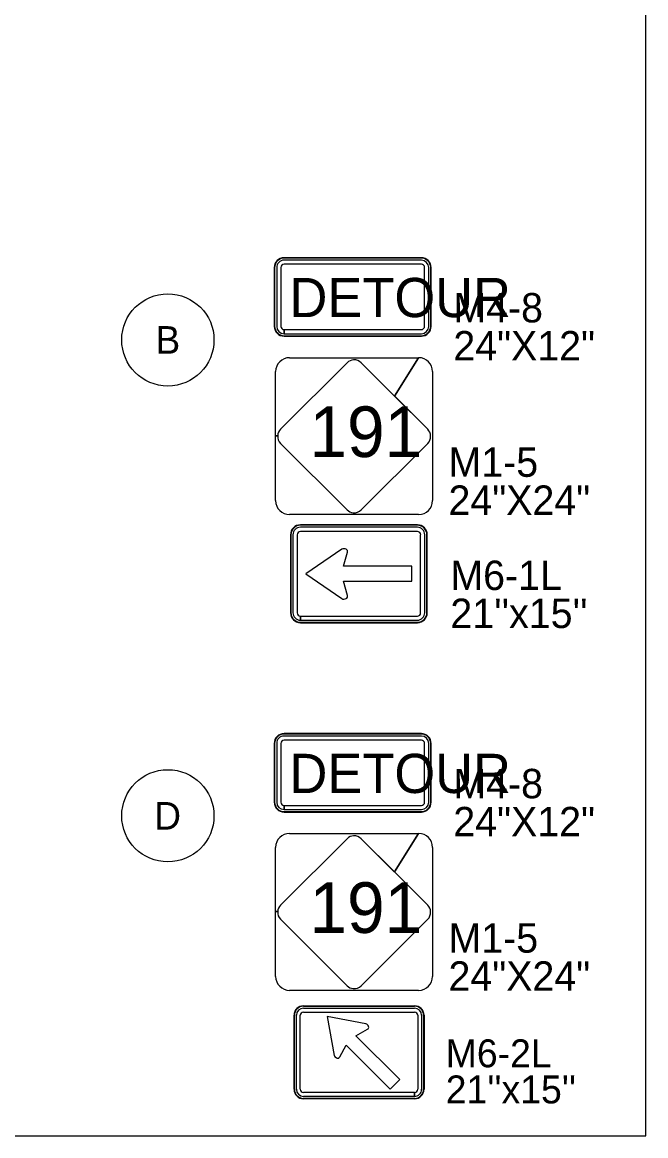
# Model space of a CAD drawing. Extents: x 886234 to 968767, y 455416 to 684046.
# Drawn here: x 926108 to 929770, y 569803 to 576347 of the extents above; entities that cross this region are included whole.
import ezdxf

# ---------------------------------------------------------------- set-up
doc = ezdxf.new("R2010")
doc.units = 0
for name, color, linetype in [('Scratch_Level_4', 7, 'Continuous'), ('TC DEV SIGN BLACK 239', 7, 'Continuous'), ('TC DEV SIGN BLACK ZERO', 7, 'Continuous'), ('TC DEV SIGN ORANGE', 7, 'Continuous'), ('TC DEV SIGN WHITE', 7, 'Continuous'), ('TC LABEL TEXT', 7, 'Continuous')]:
    doc.layers.add(name, color=color, linetype=linetype)

msp = doc.modelspace()

# ---------------------------------------------------------------- linework, layer by layer
at = {"layer": 'Scratch_Level_4'}
for p, q in [((929770.3, 569803.5), (929770.3, 581930.6)), ((922390.1, 569803.5), (929770.3, 569803.5))]:
    msp.add_line(p, q, dxfattribs=at)
at = {"layer": 'TC DEV SIGN BLACK 239'}
for p, q in [((927677.4, 574375.8), (928056.9, 574375.8)), ((927677.4, 574375.8), (927677.4, 574375.8)), ((927677.4, 574375.8), (928436.3, 574375.8)), ((927677.4, 574375.8), (927677.4, 574375.8)), ((928056.9, 574375.8), (928436.3, 574375.8)), ((928294.4, 574150.5), (928436.3, 574375.8)), ((928015.6, 574345.7), (927625.3, 573955.4)), ((927596, 573917.3), (927596, 574294.5)), ((927596, 573917.3), (927596, 574294.5)), ((928517.7, 574294.5), (928517.7, 573535.5)), ((928517.7, 574294.5), (928517.7, 573535.5)), ((928489.5, 573955.4), (928294.4, 574150.5)), ((927608.1, 573917.3), (927596, 573917.3)), ((927596, 573917.1), (927608.1, 573917.1)), ((927596, 573535.5), (927596, 573917.1)), ((927596, 573535.5), (927596, 573917.1)), ((927625.3, 573871.7), (928015.6, 573481.5)), ((928099.2, 573481.5), (928489.5, 573871.7)), ((928436.3, 573454.2), (927677.4, 573454.2)), ((928056.9, 573454.2), (927677.4, 573454.2)), ((928436.3, 573454.2), (928056.9, 573454.2)), ((927697.9, 573335), (927697.9, 572877)), ((927722.2, 573335), (927722.2, 572877)), ((928428.7, 573378.8), (927741.7, 573378.8)), ((928428.7, 573354.4), (927741.7, 573354.4)), ((928448.1, 572877), (928448.1, 573335)), ((928472.4, 572877), (928472.5, 573335)), ((927984.9, 573250.5), (927773.7, 573105)), ((927994, 573149.9), (928017.9, 573232.7)), ((928397.1, 573149.9), (927994, 573149.9)), ((928397.1, 573061.7), (928397.1, 573149.9)), ((927773.7, 573105), (927984.9, 572959.6)), ((928017.9, 572977.3), (927994.1, 573061.7)), ((927994.1, 573061.7), (928397.1, 573061.7)), ((927741.7, 572833.1), (927741.7, 572857.5)), ((927741.9, 572857.5), (928428.6, 572857.5)), ((927741.9, 572857.5), (927741.9, 572833.1)), ((927741.9, 572833.1), (928428.6, 572833.1)), ((927677.4, 571579.3), (928056.9, 571579.3)), ((927677.4, 571579.3), (927677.4, 571579.3)), ((927677.4, 571579.3), (928436.3, 571579.3)), ((927677.4, 571579.3), (927677.4, 571579.3)), ((928056.9, 571579.3), (928436.3, 571579.3)), ((928294.4, 571354), (928436.3, 571579.3)), ((927596, 571120.8), (927596, 571498)), ((927596, 571120.8), (927596, 571498)), ((928015.6, 571549.2), (927625.3, 571158.9)), ((928517.7, 571498), (928517.7, 570739.1)), ((928517.7, 571498), (928517.7, 570739.1)), ((928489.5, 571158.9), (928294.4, 571354)), ((927608.1, 571120.8), (927596, 571120.8)), ((927596, 571120.6), (927608.1, 571120.6)), ((927596, 570739.1), (927596, 571120.6)), ((927596, 570739.1), (927596, 571120.6)), ((927625.3, 571075.3), (928015.6, 570685)), ((928099.2, 570685), (928489.5, 571075.3)), ((928436.3, 570657.7), (927677.4, 570657.7)), ((928056.9, 570657.7), (927677.4, 570657.7)), ((928436.3, 570657.7), (928056.9, 570657.7)), ((927718.1, 570076.3), (927718, 570511.4)), ((927741.2, 570076.3), (927741.2, 570511.4)), ((927759.7, 570553.1), (928412.3, 570553.1)), ((927759.7, 570529.9), (928412.3, 570529.9)), ((928430.8, 570511.4), (928430.8, 570076.3)), ((928453.9, 570511.4), (928453.9, 570076.3)), ((928126, 570461.6), (927898.4, 570503.5)), ((927898.4, 570503.5), (927940.3, 570275.9)), ((928067.6, 570391.5), (928135.7, 570429.2)), ((928324.9, 570134.3), (928067.6, 570391.5)), ((927972.7, 570266.2), (928011.4, 570335.2)), ((928011.4, 570335.2), (928268.6, 570078)), ((928268.6, 570078), (928324.9, 570134.3)), ((928412.1, 570057.8), (927759.7, 570057.8)), ((928412.1, 570057.8), (928412.1, 570034.7)), ((928412.3, 570034.7), (928412.3, 570057.8)), ((928412.1, 570034.7), (927759.7, 570034.7))]:
    msp.add_line(p, q, dxfattribs=at)
for points in [[(928436.3, 574375.8), (928294.4, 574150.5), (928099.2, 574345.7)], [(928436.3, 571579.3), (928294.4, 571354), (928099.2, 571549.2)]]:
    msp.add_lwpolyline(points, dxfattribs=at)
for centre, radius, start, end in [((927677.4, 574294.5), 81.3, 90, 180), ((927677.4, 574294.5), 81.3, 90, 180), ((928436.3, 574294.5), 81.3, 360, 90), ((928436.3, 574294.5), 81.3, 360, 90), ((928057.4, 574303.9), 59.1, 93.21024, 135), ((928057.4, 574303.9), 59.1, 45, 93.07635), ((927667.1, 573913.6), 59.1, 176.55952, 225), ((927667.1, 573913.6), 59.1, 135, 176.407), ((928447.7, 573913.6), 59.1, 1.92932, 45), ((928447.7, 573913.6), 59.1, 315, 1.73824), ((927677.4, 573535.5), 81.3, 180, 270), ((927677.4, 573535.5), 81.3, 180, 270), ((928436.3, 573535.5), 81.3, 270, 360), ((928436.3, 573535.5), 81.3, 270, 360), ((928057.4, 573523.3), 59.1, 225, 265.0473), ((928057.4, 573523.3), 59.1, 265.18148, 315), ((927677.4, 571498), 81.3, 90, 180), ((927677.4, 571498), 81.3, 90, 180), ((928057.4, 571507.4), 59.1, 93.21024, 135), ((928057.4, 571507.4), 59.1, 45, 93.07635), ((928436.3, 571498), 81.3, 360, 90), ((928436.3, 571498), 81.3, 360, 90), ((927667.1, 571117.1), 59.1, 176.55952, 225), ((927667.1, 571117.1), 59.1, 135, 176.407), ((928447.7, 571117.1), 59.1, 1.92932, 45), ((928447.7, 571117.1), 59.1, 315, 1.73824), ((927677.4, 570739.1), 81.3, 180, 270), ((927677.4, 570739.1), 81.3, 180, 270), ((928436.3, 570739.1), 81.3, 270, 360), ((928436.3, 570739.1), 81.3, 270, 360), ((928057.4, 570726.8), 59.1, 225, 265.0473), ((928057.4, 570726.8), 59.1, 265.18148, 315)]:
    msp.add_arc(centre, radius, start, end, dxfattribs=at)
for centre, major_axis, ratio, start_param, end_param in [((927741.7, 573335), (43.8, 0), 0.999865, 1.570796, 3.141593), ((927741.7, 573335), (19.5, 0), 0.999865, 1.570796, 3.141593), ((928428.7, 573335), (43.8, 0), 0.999865, 0, 1.570796), ((928428.7, 573335), (19.5, 0), 0.999865, 0, 1.570796), ((927997.2, 573237.5), (-21.7, 0), 0.720018, 2.830616, 5.313575), ((927997.2, 572972.5), (-21.7, 0), 0.720018, 0.969609, 3.452568), ((927741.7, 572877), (43.8, 0), 0.999865, 3.141593, 4.712389), ((927741.7, 572877), (19.5, 0), 0.999865, 3.141593, 4.712389), ((928428.6, 572877), (43.8, 0), 0.999865, 4.712389, 6.283185), ((928428.6, 572877), (19.5, 0), 0.999865, 4.712389, 6.283185), ((927759.7, 570511.4), (-41.6, 0), 0.999865, 4.712389, 6.283185), ((927759.7, 570511.4), (-18.5, 0), 0.999865, 4.712389, 6.283185), ((928412.3, 570511.4), (-41.6, 0), 0.999865, 3.141593, 4.712389), ((928412.3, 570511.4), (-18.5, 0), 0.999865, 3.141593, 4.712389), ((928125.6, 570445.5), (-13.9, 13.9), 0.720018, 2.830616, 5.313575), ((927956.4, 570276.3), (-13.9, 13.9), 0.720018, 0.969609, 3.452568), ((927759.7, 570076.3), (-41.6, 0), 0.999865, 0, 1.570796), ((927759.7, 570076.3), (-18.5, 0), 0.999865, 0, 1.570796), ((928412.3, 570076.3), (-41.6, 0), 0.999865, 1.570796, 3.141593), ((928412.3, 570076.3), (-18.5, 0), 0.999865, 1.570796, 3.141593)]:
    msp.add_ellipse(centre, major_axis=major_axis, ratio=ratio, start_param=start_param, end_param=end_param, dxfattribs=at)
at = {"layer": 'TC DEV SIGN BLACK ZERO'}
for p, q in [((928452.1, 574963.1), (927645.6, 574963.1)), ((927645.6, 574960.7), (927645.6, 574960.7)), ((928452.1, 574960.7), (927645.6, 574960.7)), ((928452.1, 574960.7), (928452.1, 574960.7)), ((927588, 574905.5), (927588, 574559.9)), ((927590.4, 574905.5), (927590.4, 574559.9)), ((927590.4, 574905.5), (927590.4, 574905.5)), ((927602.4, 574905.5), (927602.4, 574559.9)), ((927626.4, 574905.5), (927626.4, 574559.9)), ((928452.1, 574948.7), (927645.6, 574948.7)), ((928452.1, 574924.7), (927645.6, 574924.7)), ((928471.3, 574559.9), (928471.3, 574905.5)), ((928495.3, 574559.9), (928495.3, 574905.5)), ((928507.3, 574905.5), (928507.4, 574905.5)), ((928507.4, 574559.9), (928507.4, 574905.5)), ((928509.7, 574559.9), (928509.7, 574905.5)), ((927590.4, 574559.9), (927590.4, 574559.9)), ((927645.6, 574516.7), (927645.6, 574540.7)), ((927645.6, 574502.3), (927645.6, 574504.7)), ((927645.6, 574504.7), (927645.6, 574504.7)), ((927645.7, 574504.7), (928452.1, 574504.7)), ((927645.7, 574504.7), (927645.7, 574502.3)), ((927645.7, 574502.3), (928452.1, 574502.3)), ((927645.9, 574540.7), (928452.1, 574540.7)), ((927645.9, 574540.7), (927645.9, 574516.7)), ((927645.9, 574516.7), (928452.1, 574516.7)), ((928452.1, 574504.7), (928452.1, 574504.7)), ((928507.4, 574559.9), (928507.3, 574559.9)), ((928428.7, 573393.4), (927741.7, 573393.4)), ((927741.7, 573390.9), (927741.7, 573391)), ((928428.7, 573390.9), (927741.7, 573391)), ((928428.7, 573390.9), (928428.7, 573390.9)), ((927683.3, 573335), (927683.3, 572877)), ((927685.7, 573335), (927685.7, 572877)), ((927685.7, 573335), (927685.7, 573335)), ((928484.6, 573335), (928484.7, 573335)), ((928484.6, 572877), (928484.7, 573335)), ((928487.1, 572877), (928487.1, 573335)), ((927685.7, 572877), (927685.7, 572877)), ((928484.6, 572877), (928484.6, 572877)), ((927741.7, 572818.5), (927741.7, 572821)), ((927741.7, 572821), (927741.7, 572821)), ((927741.7, 572821), (928428.6, 572821)), ((927741.7, 572821), (927741.7, 572818.5)), ((927741.7, 572818.5), (928428.6, 572818.5)), ((928428.6, 572821), (928428.6, 572821)), ((928452.1, 572166.6), (927645.6, 572166.6)), ((927645.6, 572164.2), (927645.6, 572164.2)), ((928452.1, 572164.2), (927645.6, 572164.2)), ((928452.1, 572152.2), (927645.6, 572152.2)), ((928452.1, 572164.2), (928452.1, 572164.2)), ((927588, 572109), (927588, 571763.4)), ((927590.4, 572109), (927590.4, 571763.4)), ((927590.4, 572109), (927590.4, 572109)), ((927602.4, 572109), (927602.4, 571763.4)), ((927626.4, 572109), (927626.4, 571763.4)), ((928452.1, 572128.2), (927645.6, 572128.2)), ((928471.3, 571763.4), (928471.3, 572109)), ((928495.3, 571763.4), (928495.3, 572109)), ((928507.3, 572109), (928507.4, 572109)), ((928507.4, 571763.4), (928507.4, 572109)), ((928509.7, 571763.4), (928509.7, 572109)), ((927590.4, 571763.4), (927590.4, 571763.4)), ((928507.4, 571763.4), (928507.3, 571763.4)), ((927645.6, 571720.2), (927645.6, 571744.2)), ((927645.6, 571705.8), (927645.6, 571708.2)), ((927645.6, 571708.2), (927645.6, 571708.2)), ((927645.7, 571708.2), (928452.1, 571708.2)), ((927645.7, 571708.2), (927645.7, 571705.8)), ((927645.7, 571705.8), (928452.1, 571705.8)), ((927645.9, 571744.2), (928452.1, 571744.2)), ((927645.9, 571744.2), (927645.9, 571720.2)), ((927645.9, 571720.2), (928452.1, 571720.2)), ((928452.1, 571708.2), (928452.1, 571708.2)), ((927704.2, 570076.3), (927704.2, 570511.4)), ((927706.5, 570511.4), (927706.5, 570511.4)), ((927706.5, 570076.3), (927706.5, 570511.4)), ((927759.7, 570566.9), (928412.3, 570566.9)), ((927759.7, 570564.6), (928412.3, 570564.6)), ((927759.7, 570564.6), (927759.7, 570564.6)), ((928412.3, 570564.6), (928412.3, 570564.6)), ((928465.5, 570511.4), (928465.4, 570511.4)), ((928465.5, 570511.4), (928465.5, 570076.3)), ((928467.8, 570511.4), (928467.8, 570076.3)), ((927706.5, 570076.3), (927706.5, 570076.3)), ((928465.5, 570076.3), (928465.5, 570076.3)), ((927759.7, 570023.1), (927759.7, 570023.2)), ((928412.2, 570023.2), (927759.7, 570023.2)), ((928412.2, 570020.8), (927759.7, 570020.8)), ((928412.2, 570023.2), (928412.2, 570020.8)), ((928412.3, 570020.8), (928412.3, 570023.2)), ((928412.3, 570023.2), (928412.3, 570023.1))]:
    msp.add_line(p, q, dxfattribs=at)
for centre, major_axis, start_param, end_param in [((927645.6, 574905.5), (57.6, 0), 1.570796, 3.141593), ((927645.6, 574905.5), (55.2, 0), 1.570796, 3.141593), ((928452.1, 574905.5), (57.6, 0), 0, 1.570796), ((928452.1, 574905.5), (55.2, 0), 0, 1.570796), ((927645.6, 574905.5), (43.2, 0), 1.570796, 3.141593), ((927645.6, 574905.5), (19.2, 0), 1.570796, 3.141593), ((928452.1, 574905.5), (43.2, 0), 0, 1.570796), ((928452.1, 574905.5), (19.2, 0), 0, 1.570796), ((927645.6, 574559.9), (57.6, 0), 3.141593, 4.712389), ((927645.6, 574559.9), (55.2, 0), 3.141593, 4.712389), ((927645.6, 574559.9), (43.2, 0), 3.141593, 4.712389), ((927645.6, 574559.9), (19.2, 0), 3.141593, 4.712389), ((928452.1, 574559.9), (43.2, 0), 4.712389, 6.283185), ((928452.1, 574559.9), (19.2, 0), 4.712389, 6.283185), ((928452.1, 574559.9), (57.6, 0), 4.712389, 6.283185), ((928452.1, 574559.9), (55.2, 0), 4.712389, 6.283185), ((927741.7, 573335), (58.4, 0), 1.570796, 3.141593), ((927741.7, 573335), (56, 0), 1.570796, 3.141593), ((928428.7, 573335), (58.4, 0), 0, 1.570796), ((928428.7, 573335), (56, 0), 0, 1.570796), ((927741.7, 572877), (58.4, 0), 3.141593, 4.712389), ((927741.7, 572877), (56, 0), 3.141593, 4.712389), ((928428.6, 572877), (58.4, 0), 4.712389, 6.283185), ((928428.6, 572877), (56, 0), 4.712389, 6.283185), ((927645.6, 572109), (57.6, 0), 1.570796, 3.141593), ((927645.6, 572109), (55.2, 0), 1.570796, 3.141593), ((927645.6, 572109), (43.2, 0), 1.570796, 3.141593), ((928452.1, 572109), (57.6, 0), 0, 1.570796), ((928452.1, 572109), (55.2, 0), 0, 1.570796), ((928452.1, 572109), (43.2, 0), 0, 1.570796), ((927645.6, 572109), (19.2, 0), 1.570796, 3.141593), ((928452.1, 572109), (19.2, 0), 0, 1.570796), ((927645.6, 571763.4), (57.6, 0), 3.141593, 4.712389), ((927645.6, 571763.4), (55.2, 0), 3.141593, 4.712389), ((927645.6, 571763.4), (43.2, 0), 3.141593, 4.712389), ((927645.6, 571763.4), (19.2, 0), 3.141593, 4.712389), ((928452.1, 571763.4), (43.2, 0), 4.712389, 6.283185), ((928452.1, 571763.4), (19.2, 0), 4.712389, 6.283185), ((928452.1, 571763.4), (57.6, 0), 4.712389, 6.283185), ((928452.1, 571763.4), (55.2, 0), 4.712389, 6.283185), ((927759.7, 570511.4), (-55.5, 0), 4.712389, 6.283185), ((927759.7, 570511.4), (-53.2, 0), 4.712389, 6.283185), ((928412.3, 570511.4), (-55.5, 0), 3.141593, 4.712389), ((928412.3, 570511.4), (-53.2, 0), 3.141593, 4.712389), ((927759.7, 570076.3), (-55.5, 0), 0, 1.570796), ((927759.7, 570076.3), (-53.2, 0), 0, 1.570796), ((928412.3, 570076.3), (-55.5, 0), 1.570796, 3.141593), ((928412.3, 570076.3), (-53.2, 0), 1.570796, 3.141593)]:
    msp.add_ellipse(centre, major_axis=major_axis, ratio=0.999865, start_param=start_param, end_param=end_param, dxfattribs=at)
at = {"layer": 'TC DEV SIGN ORANGE'}
for p, q in [((928452.1, 574963.1), (927645.6, 574963.1)), ((927588, 574905.5), (927588, 574559.9)), ((928509.7, 574559.9), (928509.7, 574905.5)), ((927645.6, 574502.3), (928452.1, 574502.3)), ((928452.1, 572166.6), (927645.6, 572166.6)), ((927588, 572109), (927588, 571763.4)), ((928509.7, 571763.4), (928509.7, 572109)), ((927645.6, 571705.8), (928452.1, 571705.8))]:
    msp.add_line(p, q, dxfattribs=at)
for centre, start_param, end_param in [((927645.6, 574905.5), 1.570796, 3.141593), ((928452.1, 574905.5), 0, 1.570796), ((927645.6, 574559.9), 3.141593, 4.712389), ((928452.1, 574559.9), 4.712389, 6.283185), ((927645.6, 572109), 1.570796, 3.141593), ((928452.1, 572109), 0, 1.570796), ((927645.6, 571763.4), 3.141593, 4.712389), ((928452.1, 571763.4), 4.712389, 6.283185)]:
    msp.add_ellipse(centre, major_axis=(57.6, 0), ratio=0.999865, start_param=start_param, end_param=end_param, dxfattribs=at)
at = {"layer": 'TC DEV SIGN WHITE'}
for p, q in [((927625.3, 573955.4), (928015.6, 574345.7)), ((928015.6, 574345.7), (927625.3, 573955.4)), ((928099.2, 574345.7), (928489.5, 573955.4)), ((928099.2, 574345.7), (928099.2, 574345.7)), ((928489.5, 573955.4), (928099.2, 574345.7)), ((927608.1, 573917.1), (927608.1, 573917.1)), ((927625.3, 573871.8), (928015.6, 573481.5)), ((928015.6, 573481.5), (927625.3, 573871.7)), ((928099.2, 573481.5), (928489.5, 573871.8)), ((928489.5, 573871.7), (928099.2, 573481.5)), ((928428.7, 573393.4), (927741.7, 573393.4)), ((927683.3, 573335), (927683.3, 572877)), ((928487.1, 572877), (928487.1, 573335)), ((927741.7, 572818.5), (928428.6, 572818.5)), ((927625.3, 571158.9), (928015.6, 571549.2)), ((928015.6, 571549.2), (927625.3, 571158.9)), ((928099.2, 571549.2), (928489.5, 571158.9)), ((928099.2, 571549.2), (928099.2, 571549.2)), ((928489.5, 571158.9), (928099.2, 571549.2)), ((927608.1, 571120.6), (927608.1, 571120.6)), ((928015.6, 570685), (927625.3, 571075.3)), ((927625.3, 571075.3), (928015.6, 570685)), ((928489.5, 571075.3), (928099.2, 570685)), ((928099.2, 570685), (928489.5, 571075.3)), ((927704.2, 570076.3), (927704.2, 570511.4)), ((927759.7, 570566.9), (928412.3, 570566.9)), ((928467.8, 570511.4), (928467.8, 570076.3)), ((928412.3, 570020.8), (927759.7, 570020.8))]:
    msp.add_line(p, q, dxfattribs=at)
for points in [[(928054.2, 574362.9), (928054.1, 574362.9)], [(927608.1, 573917.3), (927608.1, 573917.3), (927608.1, 573917.1)], [(928506.8, 573915.4), (928506.8, 573915.6)], [(928052.3, 573464.4), (928052.4, 573464.4)], [(928054.2, 571566.4), (928054.1, 571566.4)], [(927608.1, 571120.8), (927608.1, 571120.8), (927608.1, 571120.6)], [(928506.8, 571118.9), (928506.8, 571119.1)], [(928052.3, 570667.9), (928052.4, 570667.9)]]:
    msp.add_lwpolyline(points, dxfattribs=at)
for centre, start, end in [((928057.4, 574303.9), 93.21024, 135), ((928057.4, 574303.9), 93.21024, 135), ((928057.4, 574303.9), 45, 93.07635), ((928057.4, 574303.9), 45, 93.07635), ((927667.1, 573913.6), 176.55952, 225), ((927667.1, 573913.6), 176.56019, 225), ((927667.1, 573913.6), 135, 176.407), ((927667.1, 573913.6), 135, 176.407), ((928447.7, 573913.6), 1.92932, 45), ((928447.7, 573913.6), 1.92932, 45), ((928447.7, 573913.6), 315, 1.73824), ((928447.7, 573913.6), 315, 1.73824), ((928057.4, 573523.3), 225, 265.0473), ((928057.4, 573523.3), 225, 265.0473), ((928057.4, 573523.3), 265.18148, 315), ((928057.4, 573523.3), 265.18148, 315), ((928057.4, 571507.4), 93.21024, 135), ((928057.4, 571507.4), 93.21024, 135), ((928057.4, 571507.4), 45, 93.07635), ((928057.4, 571507.4), 45, 93.07635), ((927667.1, 571117.1), 176.55952, 225), ((927667.1, 571117.1), 176.56019, 225), ((927667.1, 571117.1), 135, 176.407), ((927667.1, 571117.1), 135, 176.407), ((928447.7, 571117.1), 1.92932, 45), ((928447.7, 571117.1), 1.92932, 45), ((928447.7, 571117.1), 315, 1.73824), ((928447.7, 571117.1), 315, 1.73824), ((928057.4, 570726.8), 225, 265.0473), ((928057.4, 570726.8), 225, 265.0473), ((928057.4, 570726.8), 265.18148, 315), ((928057.4, 570726.8), 265.18148, 315)]:
    msp.add_arc(centre, 59.1, start, end, dxfattribs=at)
for centre, major_axis, start_param, end_param in [((927741.7, 573335), (58.4, 0), 1.570796, 3.141593), ((928428.7, 573335), (58.4, 0), 0, 1.570796), ((927741.7, 572877), (58.4, 0), 3.141593, 4.712389), ((928428.6, 572877), (58.4, 0), 4.712389, 6.283185), ((927759.7, 570511.4), (-55.5, 0), 4.712389, 6.283185), ((928412.3, 570511.4), (-55.5, 0), 3.141593, 4.712389), ((927759.7, 570076.3), (-55.5, 0), 0, 1.570796), ((928412.3, 570076.3), (-55.5, 0), 1.570796, 3.141593)]:
    msp.add_ellipse(centre, major_axis=major_axis, ratio=0.999865, start_param=start_param, end_param=end_param, dxfattribs=at)
at = {"layer": 'TC LABEL TEXT'}
for centre in [(926963, 574480.1), (926963, 571683.6)]:
    msp.add_circle(centre, 270.9, dxfattribs=at)

# ---------------------------------------------------------------- texts
at = {"layer": 'TC DEV SIGN BLACK 239'}
for p in [(927794.2, 573791.9), (927794.2, 570995.4)]:
    msp.add_text('191', height=297.3, rotation=360, dxfattribs=at).set_placement(p)
at = {"layer": 'TC DEV SIGN BLACK ZERO'}
for s, height, p in [('DETOUR', 230.4, (927677.6, 574614)), ('M4-8', 172.8, (928640.1, 574583)), ('24"X12"', 172.8, (928640.1, 574359.5)), ('M1-5', 172.8, (928611.7, 573675.6)), ('24"X24"', 172.8, (928611.7, 573452.1)), ('M6-1L', 172.8, (928622.6, 573010.5)), ("21''x15''", 172.8, (928622.6, 572787)), ('DETOUR', 230.4, (927677.6, 571817.5)), ('M4-8', 172.8, (928640.1, 571786.5)), ('24"X12"', 172.8, (928640.1, 571563)), ('M1-5', 172.8, (928611.7, 570879.1)), ('24"X24"', 172.8, (928611.7, 570655.6)), ('M6-2L', 164.16, (928595.3, 570205.7)), ("21''x15''", 164.16, (928595.3, 569993.4))]:
    msp.add_text(s, height=height, rotation=360, dxfattribs=at).set_placement(p)
at = {"layer": 'TC LABEL TEXT'}
for s, p in [('B', (926890.9, 574399.1)), ('D', (926883.7, 571602.6))]:
    msp.add_text(s, height=162, dxfattribs=at).set_placement(p)

doc.saveas('drawing.dxf')
